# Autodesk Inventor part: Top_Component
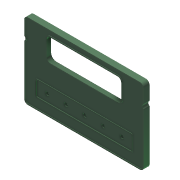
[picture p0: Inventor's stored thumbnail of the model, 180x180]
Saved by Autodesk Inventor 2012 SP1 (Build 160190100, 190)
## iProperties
Created: 2006-01
Part Number: Top_Component
Document SubType Name: Modeling
Designer: t_munrn
Density: 1 g/cm^3
Material: Default
Author: t_munrn
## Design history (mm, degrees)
sketch "Sketch1"
  geometry: L1 (-240, 152.5)-(240, 152.5); L2 (240, 152.5)-(240, -152.5); L3 (240, -152.5)-(-240, -152.5); L4 (-240, -152.5)-(-240, 152.5); L5 (-240, 152.5)-(240, -152.5); 2 further points
  constraints: 10 end point, 2 parallel, 1 coincident, 1 horizontal, 1 midpoint, 1 perpendicular
  dimensions: "d1" = 480 distance of L1.start L1.end; "d2" = 305 distance of L3.end L1.start
extrude "Extrusion1" new body sketch "Sketch1" stored distance "d3" = 24; taper "d4" = 0 deg
sketch "Sketch2"
  geometry: L1 (200, -115)-(-200, -115); L2 (-200, -115)-(-200, -40); L3 (-200, -40)-(200, -40); L4 (200, -40)-(200, -115); 2 further points
  constraints: 8 end point, 2 parallel, 1 horizontal, 1 midpoint, 1 perpendicular, 1 vertical alignment
  dimensions: "d5" = 400 distance of L1.start L1.end; "d6" = 40 distance from line of point (0, 0) L3; "d7" = 75 distance of L3.end L1.start
extrude "Extrusion2" join sketch "Sketch2" distance "d8" = 25; taper "d9" = 0 deg
fillet "Fillet1" dims "d10" = 12
sketch "Sketch3"
  geometry: L1 (-200, -103)-(-200, -52) reference; L2 (188, -115)-(-188, -115) reference; L3 (200, -52)-(200, -103) reference; L4 (-188, -40)-(188, -40) reference; L5 (-194, -103)-(-194, -52); L6 (-188, -46)-(188, -46); L7 (194, -52)-(194, -103); L8 (188, -109)-(-188, -109); A1 r 12 centre (-188, -52) between (-188, -40) and (-200, -52) reference; A2 r 12 centre (-188, -103) between (-200, -103) and (-188, -115) reference; A3 r 12 centre (188, -103) between (188, -115) and (200, -103) reference; A4 r 12 centre (188, -52) between (200, -52) and (188, -40) reference; A5 r 6 centre (-188, -103) between (-194, -103) and (-188, -109); A6 r 6 centre (-188, -52) between (-188, -46) and (-194, -52); A7 r 6 centre (188, -52) between (194, -52) and (188, -46); A8 r 6 centre (188, -103) between (188, -109) and (194, -103); 1 further point
  constraints: 8 end point, 8 point on circle, 4 centre point, 7 other
  dimensions: "d11" = 6 distance between parallel lines of L1 L5
extrude "Extrusion3" cut sketch "Sketch3" distance "d12" = 22; taper "d13" = 0 deg
fillet "Fillet2" dims "d14" = 15
sketch "Sketch5"
  geometry: L1 (188, -109)-(-188, -109) reference; L2 (194, -52)-(194, -103) reference; L3 (-188, -46)-(188, -46) reference; L4 (-194, -103)-(-194, -52) reference; L5 (188, -107)-(-188, -107); L6 (-192, -103)-(-192, -52); L7 (-188, -48)-(188, -48); L8 (192, -52)-(192, -103); A1 r 6 centre (188, -103) between (188, -109) and (194, -103) reference; A2 r 6 centre (188, -52) between (194, -52) and (188, -46) reference; A3 r 6 centre (-188, -52) between (-188, -46) and (-194, -52) reference; A4 r 6 centre (-188, -103) between (-194, -103) and (-188, -109) reference; A5 r 4 centre (188, -103) between (188, -107) and (192, -103); A6 r 4 centre (-188, -103) between (-192, -103) and (-188, -107); A7 r 4 centre (-188, -52) between (-188, -48) and (-192, -52); A8 r 4 centre (188, -52) between (192, -52) and (188, -48); 1 further point
  constraints: 8 end point, 8 point on circle, 4 centre point, 7 other
  dimensions: "d22" = 2 distance between parallel lines of L8 L2
extrude "Extrusion5" cut sketch "Sketch5" distance "d23" = 3; taper "d24" = 0 deg
sketch "Sketch6"
  geometry: L1 (-188, -46)-(188, -46) reference; L2 (-194, -103)-(-194, -52) reference; C1 r 10 at (0, -77.5); 4 further points
  constraints: 2 midpoint, 1 centre point, 1 coincident, 1 horizontal alignment, 1 vertical alignment
  dimensions: "d25" = 20 diameter of C1
extrude "Extrusion6" join sketch "Sketch6" stored distance "d26" = 3; taper "d27" = -5 deg
pattern_linear "Rectangular Pattern1" dims "d30" = 75
sketch "Sketch7"
  geometry: C1 r 8.075 at (-150, -77.5) reference; C2 r 8.075 at (-75, -77.5) reference; C3 r 8.075 at (0, -77.5) reference; C4 r 8.075 at (75, -77.5) reference; C5 r 8.075 at (150, -77.5) reference; 1 further point
hole "Hole1" sketch "Sketch7" at (150, -77.5), (75, -77.5), (0, -77.5), (-75, -77.5), (-150, -77.5) diameter "d31" = 6.6; stored, may be unused: countersink angle "d35" = 90 deg, drill point angle "d37" = 118 deg; dims "d32" = 6, "d33" = 14.55, "d34" = 4.38, "d36" = 8
sketch "Sketch8"
  geometry: L1 (240, 27.5)-(240, -137.5) reference; L2 (-225, 152.5)-(225, 152.5) reference; C1 r 9.25 at (244, 73.15); 1 further point
  constraints: 1 centre point
  dimensions: "d38" = 18.5 diameter of C1; "d60" = 4 distance from line of L1 C1.centre; "d79" = 79.35 distance from line of L2 C1.centre
extrude "Extrusion7" cut sketch "Sketch8" stored distance "d39" = 10; taper "d40" = 0 deg
mirror "Mirror1"
fillet "Fillet5" dims "d41" = 5
chamfer "Chamfer2" distance "d42" = 1; stored, may be unused: second distance "d43" = 2, angle "d44" = 45 deg
sketch "Sketch13"
  geometry: L1 (-225, 152.5)-(225, 152.5) reference; L2 (135, 37.5)-(-135, 37.5); L3 (-150, 52.5)-(-150, 112.5); L4 (-135, 127.5)-(135, 127.5); L5 (150, 112.5)-(150, 52.5); L6 (-155, 52.5)-(-155, 112.5); L7 (-135, 132.5)-(135, 132.5); L8 (155, 112.5)-(155, 52.5); L9 (135, 32.5)-(-135, 32.5); A1 r 15 centre (-135, 112.5) between (-135, 127.5) and (-150, 112.5); A2 r 15 centre (135, 112.5) between (150, 112.5) and (135, 127.5); A3 r 15 centre (135, 52.5) between (135, 37.5) and (150, 52.5); A4 r 15 centre (-135, 52.5) between (-150, 52.5) and (-135, 37.5); A5 r 20 centre (-135, 52.5) between (-155, 52.5) and (-135, 32.5); A6 r 20 centre (-135, 112.5) between (-135, 132.5) and (-155, 112.5); A7 r 20 centre (135, 112.5) between (155, 112.5) and (135, 132.5); A8 r 20 centre (135, 52.5) between (135, 32.5) and (155, 52.5); 2 further points
  constraints: 16 end point, 16 point on circle, 8 centre point, 8 tangent, 4 parallel, 3 equal radius, 2 perpendicular, 1 horizontal, 1 midpoint, 1 vertical alignment, 7 other
  dimensions: "d62" = 15 radius of A1; "d63" = 90 distance between parallel lines of L2 L4; "d64" = 25 distance between parallel lines of L1 L4; "d65" = 300 distance between parallel lines of L3 L5; "d66" = 5 distance between parallel lines of L7 L4
extrude "Extrusion12" cut sketch "Sketch13" distance "d67" = 8; taper "d68" = 0 deg
sketch "Sketch14"
  geometry: L1 (135, 127.5)-(-135, 127.5) reference; L2 (-150, 112.5)-(-150, 52.5) reference; L3 (-135, 37.5)-(135, 37.5) reference; L4 (150, 52.5)-(150, 112.5) reference; A1 r 15 centre (-135, 112.5) between (-135, 127.5) and (-150, 112.5) reference; A2 r 15 centre (-135, 52.5) between (-150, 52.5) and (-135, 37.5) reference; A3 r 15 centre (135, 52.5) between (135, 37.5) and (150, 52.5) reference; A4 r 15 centre (135, 112.5) between (150, 112.5) and (135, 127.5) reference; 1 further point
extrude "Extrusion13" cut sketch "Sketch14" stored distance "d69" = 4; taper "d70" = 0 deg
chamfer "Chamfer4" distance "d71" = 1; stored, may be unused: second distance "d72" = 2, angle "d73" = 60 deg
sketch "Sketch15"
  geometry: L1 (150, 112.5)-(150, 52.5) reference; L2 (135, 37.5)-(-135, 37.5) reference; L3 (-150, 52.5)-(-150, 112.5) reference; L4 (-135, 127.5)-(135, 127.5) reference; L5 (-240, -137.5)-(-240, 62.102) reference; L6 (225, -152.5)-(-225, -152.5) reference; L7 (240, 62.102)-(240, -137.5) reference; L8 (240, 137.5)-(240, 84.198) reference; L9 (-225, 152.5)-(225, 152.5) reference; L10 (-240, 84.198)-(-240, 137.5) reference; L11 (192, -52)-(192, -103) reference; L12 (188, -107)-(-188, -107) reference; L13 (-192, -103)-(-192, -52) reference; L14 (-188, -48)-(188, -48) reference; L15 (236, 62.102)-(236, -137.5); L16 (225, -148.5)-(-225, -148.5); L17 (-236, -137.5)-(-236, 62.102); L18 (-236, 84.198)-(-236, 137.5); L19 (-225, 148.5)-(225, 148.5); L20 (236, 137.5)-(236, 84.198); L21 (188, -44)-(-188, -44); L22 (-196, -52)-(-196, -103); L23 (-188, -111)-(188, -111); L24 (196, -103)-(196, -52); L25 (-135, 33.5)-(135, 33.5); L26 (154, 52.5)-(154, 112.5); L27 (135, 131.5)-(-135, 131.5); L28 (-154, 112.5)-(-154, 52.5); A1 r 15 centre (135, 112.5) between (150, 112.5) and (135, 127.5) reference; A2 r 15 centre (135, 52.5) between (135, 37.5) and (150, 52.5) reference; A3 r 15 centre (-135, 52.5) between (-150, 52.5) and (-135, 37.5) reference; A4 r 15 centre (-135, 112.5) between (-135, 127.5) and (-150, 112.5) reference; A5 r 5 centre (-235, 84.198) between (-240, 84.198) and (-238.158, 80.322) reference; A6 r 9.25 centre (-244, 73.15) between (-238.158, 65.978) and (-238.158, 80.322) reference; A7 r 5 centre (-235, 62.102) between (-238.158, 65.978) and (-240, 62.102) reference; A8 r 15 centre (-225, -137.5) between (-240, -137.5) and (-225, -152.5) reference; A9 r 15 centre (225, -137.5) between (225, -152.5) and (240, -137.5) reference; A10 r 5 centre (235, 62.102) between (240, 62.102) and (238.158, 65.978) reference; A11 r 9.25 centre (244, 73.15) between (238.158, 80.322) and (238.158, 65.978) reference; A12 r 5 centre (235, 84.198) between (238.158, 80.322) and (240, 84.198) reference; A13 r 15 centre (225, 137.5) between (240, 137.5) and (225, 152.5) reference; A14 r 15 centre (-225, 137.5) between (-225, 152.5) and (-240, 137.5) reference; A15 r 4 centre (188, -103) between (188, -107) and (192, -103) reference; A16 r 4 centre (-188, -103) between (-192, -103) and (-188, -107) reference; A17 r 4 centre (-188, -52) between (-188, -48) and (-192, -52) reference; A18 r 4 centre (188, -52) between (192, -52) and (188, -48) reference; A19 r 1 centre (235, 84.198) between (235.632, 83.423) and (236, 84.198); A20 r 13.25 centre (244, 73.15) between (235.632, 83.423) and (235.632, 62.877); A21 r 1 centre (235, 62.102) between (236, 62.102) and (235.632, 62.877); A22 r 11 centre (225, -137.5) between (225, -148.5) and (236, -137.5); A23 r 11 centre (-225, -137.5) between (-236, -137.5) and (-225, -148.5); A24 r 1 centre (-235, 62.102) between (-235.632, 62.877) and (-236, 62.102); A25 r 13.25 centre (-244, 73.15) between (-235.632, 62.877) and (-235.632, 83.423); A26 r 1 centre (-235, 84.198) between (-236, 84.198) and (-235.632, 83.423); A27 r 11 centre (-225, 137.5) between (-225, 148.5) and (-236, 137.5); A28 r 11 centre (225, 137.5) between (236, 137.5) and (225, 148.5); A29 r 8 centre (-188, -52) between (-188, -44) and (-196, -52); A30 r 8 centre (-188, -103) between (-196, -103) and (-188, -111); A31 r 8 centre (188, -103) between (188, -111) and (196, -103); A32 r 8 centre (188, -52) between (196, -52) and (188, -44); A33 r 19 centre (135, 52.5) between (135, 33.5) and (154, 52.5); A34 r 19 centre (135, 112.5) between (154, 112.5) and (135, 131.5); A35 r 19 centre (-135, 112.5) between (-135, 131.5) and (-154, 112.5); A36 r 19 centre (-135, 52.5) between (-154, 52.5) and (-135, 33.5); 1 further point
  constraints: 36 point on circle, 28 end point, 18 centre point, 29 other
  dimensions: "d74" = 4 distance between parallel lines of L8 L20; "d75" = 4 distance between parallel lines of L25 L2 (= d74); "d76" = 4 distance between parallel lines of L14 L21 (= d74)
extrude "Extrusion14" cut sketch "Sketch15" distance "d77" = 2; taper "d78" = 0 deg
body "Solid1"
